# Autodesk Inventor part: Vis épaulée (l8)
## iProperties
Author: Flavien MARTY
Shininess: 60.0
PropertySet Name: _Private Model Information
Created: 2001-10
Part Number: Vis épaulée (l8)
Material: Par défaut
Document SubType Name: Modélisation
Designer: Flavien MARTY
Control State: 0
Master: False
Checked Out: False
PropertySet Name: Design Tracking Control
Density: 0.0
Volumn: 0.0
Area: 0.0
PropertySet Name: Model Information
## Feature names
1. Base1
